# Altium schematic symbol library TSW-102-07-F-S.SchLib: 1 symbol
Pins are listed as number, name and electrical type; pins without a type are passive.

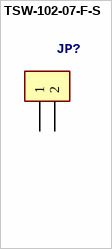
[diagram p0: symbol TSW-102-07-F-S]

## TSW-102-07-F-S
designator JP?
footprint TSW-102-07-F-S
pins: 1, 2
